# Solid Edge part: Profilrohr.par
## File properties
Username: bmolnar
Dokumentum tartalom típus: 0
Author: bmolnar
Last saved by: bmolnar
Revision: 81
Sűrűség: 0,000 kg/m^3
Pontosság: 0,990
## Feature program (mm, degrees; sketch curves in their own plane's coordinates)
base feature "unnamed BaseFeature 1"
thread "unnamed Thread 1"
thread "Menet_2"  ThreadDepth = 6 mm
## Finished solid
Body 1: solid body, 157 faces, 388 edges, 253 vertices.
  Faces by surface: plane 102, cylinder 41, cone 8, torus 6
  Edges by curve: line 284, circle 92, curve on surface 7, spline 4, intersection 1
Bounding box of the edges (mm; curved faces can reach further): 55.000 x 58.000 x 59.500, from (-27.5, -27.5, 0) to (27.5, 30.5, 59.5).
Cylindrical faces by radius (mm): R1.125 x2, R2.9 x8, R4.283 x4, R4.4 x16, R20 x1, R20.85 x2, R21.1 x2, R22.35 x2, R36.5 x4
Conical faces (half-angle, radius in mm at the cone's reference point): 30 deg R20.325 x2, 45 deg R4.783 x2, 45 deg R21.1 x2, 45 deg R21.35 x2
Toroidal faces (ring radius, tube radius in mm): R20.75 r0.1 x2, R22.15 r0.2 x4
Planar faces by outward normal: +x 9, +y 11, +z 8, -x 9, -y 9, -z 8, oblique 48
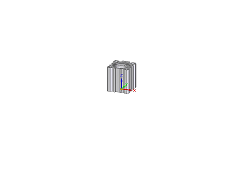
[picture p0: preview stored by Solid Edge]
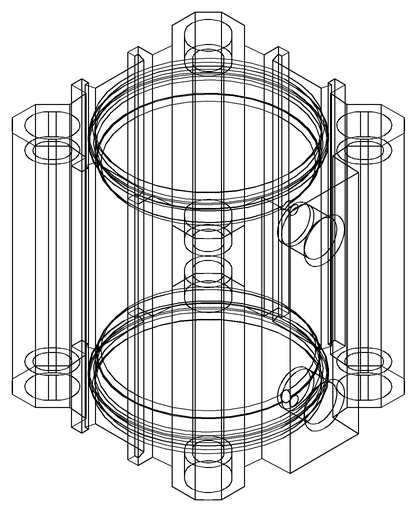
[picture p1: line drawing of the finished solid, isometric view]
